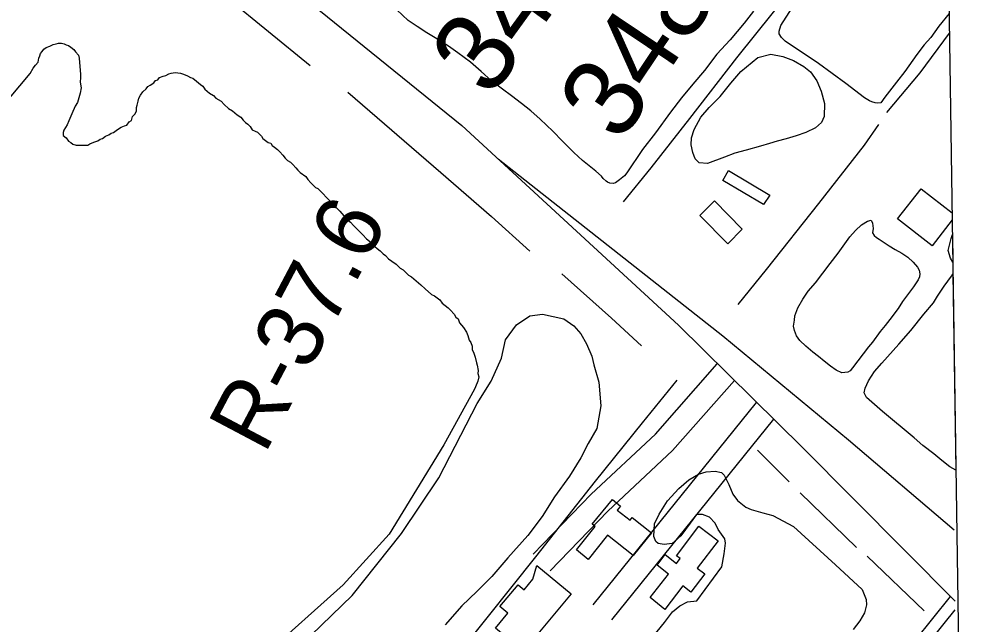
# Model space of a CAD drawing. Extents: x 3775218 to 3813389, y 343470 to 369318.
# Drawn here: x 3810057 to 3811247, y 351933 to 352694 of the extents above; entities that cross this region are included whole.
import ezdxf

# ---------------------------------------------------------------- set-up
doc = ezdxf.new("R2010")
doc.units = 0
for name, color, linetype in [('V-BLDG-OTLN', 7, 'Continuous'), ('V-GRID-FRAM', 7, 'Continuous'), ('V-RIVR-RANG-IDEN', 7, 'Continuous'), ('V-ROAD-CNTR', 7, 'Continuous'), ('V-SITE-VEGE', 7, 'Continuous'), ('V-SURV-IDEN', 7, 'Continuous'), ('V-TOPO-SHOR', 7, 'Continuous')]:
    doc.layers.add(name, color=color, linetype=linetype)

msp = doc.modelspace()

# ---------------------------------------------------------------- linework, layer by layer
at = {"layer": 'V-BLDG-OTLN'}
for p, q in [((3811163.1, 352442.5), (3811192.7, 352480.4)), ((3811192.7, 352480.4), (3811231.7, 352450)), ((3811231.7, 352450), (3811231.8, 352441.3)), ((3811206.5, 352408.7), (3811163.1, 352442.5)), ((3811231.8, 352441.3), (3811206.5, 352408.7))]:
    msp.add_line(p, q, dxfattribs=at)
for points in [[(3810994.2, 352460.4), (3810943, 352490.8), (3810950.4, 352503.2), (3811002.2, 352472.5)], [(3810949.6, 352411.1), (3810914.4, 352446.9), (3810932.7, 352465), (3810967.7, 352429.5)], [(3810830.2, 352019), (3810798, 352044.6), (3810773.8, 352014.2), (3810758.9, 352026.1), (3810782.4, 352055.7), (3810778.8, 352058.5), (3810804.2, 352089.5), (3810814.4, 352081.3), (3810810.4, 352076.3), (3810826.5, 352063.6), (3810829.1, 352066.9), (3810853.5, 352047.6)], [(3810870.1, 351951), (3810851.6, 351966.3), (3810874.8, 351995.6), (3810860.5, 352007.1), (3810870.8, 352020.2), (3810884.7, 352009.2), (3810889.4, 352015.2), (3810884.7, 352018.9), (3810913, 352056.1), (3810937.2, 352037.6), (3810911, 352003.3), (3810920.5, 351996), (3810903, 351973.1), (3810892.9, 351980.9)], [(3810752.4, 351970.7), (3810704.2, 351913.1), (3810694.4, 351921.3), (3810682.2, 351906.7), (3810656.9, 351927.8), (3810672.6, 351946.7), (3810662.6, 351955), (3810685.5, 351982.3), (3810693.2, 351975.9), (3810704.2, 351989.2), (3810709, 352006.7)]]:
    msp.add_lwpolyline(points, close=True, dxfattribs=at)
at = {"layer": 'V-GRID-FRAM'}
msp.add_lwpolyline([(3779203.7, 367073.2), (3811012.4, 367522), (3811276.9, 349341.6), (3779452.3, 348892.5), (3779203.7, 367073.2)], dxfattribs=at)
at = {"layer": 'V-ROAD-CNTR'}
for points in [[(3808873.9, 353964.1), (3810010.7, 353048.5), (3810614.6, 352560.1), (3810887.2, 352308.6), (3811043.3, 352154.9), (3811235.5, 351961.5)], [(3811234.2, 352050.9), (3811101.2, 352164.1), (3810943.3, 352295), (3810660.6, 352517.6)], [(3810704.3, 352020.6), (3810777.4, 352096.4), (3810858.4, 352171.9), (3810936.2, 352260.3)], [(3810725.9, 351999.7), (3810798.4, 352075), (3810879.9, 352151), (3810957.7, 352239.2)], [(3810780, 351957.2), (3810985.7, 352211.6)], [(3810803.3, 351938.3), (3811007.2, 352190.4)], [(3810896, 351552.5), (3811229.6, 351967.4)], [(3810907.7, 351543.1), (3811235.6, 351950.9)]]:
    msp.add_lwpolyline(points, dxfattribs=at)
at = {"layer": 'V-SITE-VEGE'}
for p, q in [((3810547.3, 352692.1), (3810533, 352705.6)), ((3810981.7, 352703.7), (3810970.1, 352688.5)), ((3811016.2, 352685.5), (3811030.3, 352707.9)), ((3811228, 352700.6), (3811215.1, 352684.7)), ((3810558.5, 352684.6), (3810547.3, 352692.1)), ((3810970.1, 352688.5), (3810952.3, 352667.7)), ((3811014.1, 352678.4), (3811016.2, 352685.5)), ((3810570.7, 352676.4), (3810558.5, 352684.6)), ((3810581.1, 352670.3), (3810570.7, 352676.4)), ((3811014.2, 352675.1), (3811014.1, 352678.4)), ((3811016.9, 352670.4), (3811014.2, 352675.1)), ((3811215.1, 352684.7), (3811205, 352670.8)), ((3810597.8, 352659.6), (3810581.1, 352670.3)), ((3810952.3, 352667.7), (3810935.7, 352649.8)), ((3811021.7, 352666.2), (3811016.9, 352670.4)), ((3811063.6, 352637.8), (3811021.7, 352666.2)), ((3811205, 352670.8), (3811196.6, 352661.3)), ((3810609.8, 352651.3), (3810597.8, 352659.6)), ((3810625.4, 352639.5), (3810609.8, 352651.3)), ((3810935.7, 352649.8), (3810920.1, 352629.3)), ((3811196.6, 352661.3), (3811187.4, 352649.4)), ((3810639.1, 352627.7), (3810625.4, 352639.5)), ((3811187.4, 352649.4), (3811172.1, 352627.7)), ((3810652.2, 352615.9), (3810639.1, 352627.7)), ((3810920.1, 352629.3), (3810905.6, 352612)), ((3811098, 352612.9), (3811063.6, 352637.8)), ((3811172.1, 352627.7), (3811161.9, 352614.4)), ((3810665.7, 352605.7), (3810652.2, 352615.9)), ((3811161.9, 352614.4), (3811147.2, 352595.7)), ((3810677.3, 352597.4), (3810665.7, 352605.7)), ((3810905.6, 352612), (3810891, 352594.8)), ((3811121.7, 352594.6), (3811098, 352612.9)), ((3810689.8, 352587.8), (3810677.3, 352597.4)), ((3810891, 352594.8), (3810877.4, 352576.7)), ((3811127.8, 352590.8), (3811121.7, 352594.6)), ((3811130.7, 352589.9), (3811127.8, 352590.8)), ((3811147.2, 352595.7), (3811142, 352588.4)), ((3810701.6, 352578.2), (3810689.8, 352587.8)), ((3811135, 352588.5), (3811130.7, 352589.9)), ((3811137.3, 352588.2), (3811135, 352588.5)), ((3811142, 352588.4), (3811137.3, 352588.2)), ((3810713.3, 352568), (3810701.6, 352578.2)), ((3810729.3, 352552.6), (3810713.3, 352568)), ((3810877.4, 352576.7), (3810858.3, 352550.6)), ((3810741.4, 352540.4), (3810729.3, 352552.6)), ((3810858.3, 352550.6), (3810842, 352529.6)), ((3810755.6, 352525.9), (3810741.4, 352540.4)), ((3810766.6, 352515.9), (3810755.6, 352525.9)), ((3810842, 352529.6), (3810822.3, 352500.2)), ((3810783.4, 352502.5), (3810766.6, 352515.9)), ((3810790.5, 352496.4), (3810783.4, 352502.5)), ((3810792.7, 352493.2), (3810790.5, 352496.4)), ((3810819.6, 352496.7), (3810813.2, 352491.7)), ((3810822.3, 352500.2), (3810819.6, 352496.7)), ((3810796.2, 352490), (3810792.7, 352493.2)), ((3810798.1, 352488.6), (3810796.2, 352490)), ((3810801, 352487.2), (3810798.1, 352488.6)), ((3810805.3, 352486.9), (3810801, 352487.2)), ((3810808.1, 352487.9), (3810805.3, 352486.9)), ((3810813.2, 352491.7), (3810808.1, 352487.9)), ((3811227, 352402.7), (3811230.7, 352417.9)), ((3811230.7, 352417.9), (3811232.1, 352422.7)), ((3811232.1, 352422.7), (3811232.6, 352388.1)), ((3811229.8, 352393.1), (3811227, 352402.7)), ((3811232.6, 352388.1), (3811229.8, 352393.1)), ((3811221.9, 352357.8), (3811231.1, 352370.6)), ((3811231.1, 352370.6), (3811232.8, 352373.2)), ((3811232.8, 352373.2), (3811236.4, 352126.3)), ((3811213.2, 352345.4), (3811221.9, 352357.8)), ((3811208.2, 352336.9), (3811213.2, 352345.4)), ((3811196.2, 352322.6), (3811208.2, 352336.9)), ((3811179.7, 352302.2), (3811196.2, 352322.6)), ((3811164.7, 352284.9), (3811179.7, 352302.2)), ((3811143.2, 352261), (3811164.7, 352284.9)), ((3811133.9, 352250.4), (3811143.2, 352261)), ((3811126.5, 352238.8), (3811133.9, 352250.4)), ((3811122.2, 352229.7), (3811126.5, 352238.8)), ((3811121.1, 352223.6), (3811122.2, 352229.7)), ((3811124.1, 352217.9), (3811121.1, 352223.6)), ((3811134, 352208.9), (3811124.1, 352217.9)), ((3811144, 352200.3), (3811134, 352208.9)), ((3811183.9, 352167.2), (3811144, 352200.3)), ((3811195.1, 352157.6), (3811183.9, 352167.2)), ((3811208.6, 352147), (3811195.1, 352157.6)), ((3811219, 352138.4), (3811208.6, 352147)), ((3811229, 352130.8), (3811219, 352138.4)), ((3811236.4, 352126.3), (3811229, 352130.8))]:
    msp.add_line(p, q, dxfattribs=at)
for points in [[(3810923.9, 352512.1), (3810913.3, 352512.9), (3810908.3, 352517.9), (3810905.5, 352525.8), (3810903.3, 352535.6), (3810903.9, 352544.6), (3810907.2, 352554.9), (3810915.5, 352570.4), (3810926.1, 352582.4), (3810939.7, 352596.2), (3810953.1, 352613.2), (3810965.9, 352628), (3810987.4, 352645.5), (3811003.5, 352649.5), (3811018.8, 352646.8), (3811032.2, 352641.5), (3811045, 352634.2), (3811053.5, 352627.4), (3811061.5, 352615.9), (3811066.9, 352602.9), (3811071.1, 352587.7), (3811070.8, 352571.3), (3811067.3, 352563.7), (3811059.8, 352556.8), (3811047.7, 352551.3), (3811035.3, 352547.1), (3811022.7, 352543.2), (3811011.7, 352540.1), (3811002, 352537.1), (3810990.6, 352534), (3810972.7, 352528.7), (3810958.2, 352525), (3810945.5, 352520)], [(3811106.5, 352255.3), (3811103.6, 352251.5), (3811100.6, 352249.8), (3811092.9, 352248.8), (3811085.8, 352252.3), (3811078.7, 352257.4), (3811070.9, 352263.4), (3811063.5, 352269.3), (3811056.6, 352274.7), (3811047.8, 352282.3), (3811040.3, 352289.4), (3811036, 352295.4), (3811033.4, 352302.3), (3811032.3, 352307.6), (3811033.2, 352315.2), (3811033.8, 352320.5), (3811037.5, 352330.5), (3811043.7, 352341.4), (3811050.8, 352351.4), (3811059.8, 352362.1), (3811078.3, 352386.5), (3811088.4, 352399.2), (3811103, 352419.7), (3811110, 352428), (3811117.7, 352435.2), (3811125.1, 352439.6), (3811129.9, 352440.9), (3811131.5, 352437.1), (3811132.4, 352430.2), (3811131.4, 352425), (3811133.8, 352421.4), (3811136.6, 352418.9), (3811139.9, 352416.9), (3811152.5, 352408.7), (3811160.1, 352404), (3811168.3, 352399.4), (3811176, 352394.2), (3811182.6, 352387.9), (3811188.1, 352381.9), (3811190.3, 352377.9), (3811191, 352373.4), (3811190.6, 352369.6), (3811188.9, 352365.8), (3811186.6, 352362), (3811183.1, 352357.1), (3811169.4, 352338.4), (3811163.7, 352329.9), (3811153.4, 352315.9), (3811147.3, 352308.5), (3811141.4, 352301), (3811131.7, 352287.4), (3811126.7, 352281.4)]]:
    msp.add_lwpolyline(points, close=True, dxfattribs=at)
for points in [[(3810476.5, 351968.7), (3810538.7, 352046.6), (3810585.8, 352117), (3810633.9, 352210.1), (3810651.8, 352238.2), (3810664.5, 352267.5), (3810669.6, 352290.5), (3810683.6, 352309.1), (3810700.2, 352320.4), (3810716.2, 352322.7), (3810743.2, 352316.9), (3810755.6, 352307.8), (3810764.5, 352297.8), (3810771.4, 352285.3), (3810778.2, 352269.8), (3810780.9, 352259.1), (3810787, 352237), (3810789.7, 352207.2), (3810784.6, 352178.7), (3810773.9, 352159.9), (3810764.3, 352141.8), (3810750, 352118.8), (3810731.3, 352092.9), (3810715.9, 352068.1), (3810697.7, 352044.4), (3810672.4, 352016.2), (3810652.4, 351992.8), (3810633.4, 351973.8), (3810614.6, 351955.8), (3810593.7, 351932)], [(3810851.2, 351912.3), (3810869.6, 351934.9), (3810880, 351948.4), (3810889, 351955.8), (3810898.7, 351961), (3810910.5, 351962), (3810942, 352004.7), (3810945, 352021), (3810946.4, 352034.5), (3810945.6, 352040), (3810937.3, 352051.8), (3810933.4, 352059.7), (3810926.3, 352067.4), (3810917.5, 352070.8), (3810910, 352070.8), (3810902.2, 352059.7), (3810890.2, 352043.7), (3810879.5, 352034.4), (3810869.5, 352032.8), (3810861.6, 352034), (3810858.9, 352036.7), (3810856.3, 352043.2), (3810857.1, 352058.9), (3810863.2, 352071.1), (3810873.7, 352087.7), (3810887.8, 352103.5), (3810900.2, 352114.4), (3810912.4, 352121.4), (3810922.4, 352124.5), (3810933.7, 352125.2), (3810941.4, 352123.4), (3810944.8, 352120), (3810950.9, 352108.3), (3810955.9, 352096.2), (3810961.6, 352088.1), (3810972, 352080), (3810979, 352077.1), (3810993.5, 352072.9), (3811006.1, 352069.6), (3811032.3, 352055.6), (3811084.9, 352007.5), (3811118.7, 351976.4), (3811123.8, 351963.6), (3811123.9, 351957), (3811121.5, 351947), (3811115.8, 351936.8), (3811107.2, 351925.9)], [(3810036, 351545.4), (3810109.4, 351638), (3810184.7, 351716.6), (3810272.8, 351796.9), (3810354.8, 351867.8), (3810425, 351919.1), (3810476.5, 351968.7)]]:
    msp.add_lwpolyline(points, dxfattribs=at)
at = {"layer": 'V-TOPO-SHOR'}
for p, q in [((3810292.4, 352743), (3810423.8, 352635.4)), ((3810987, 352151.5), (3811026.8, 352111.9)), ((3811040.7, 352098.1), (3811111.4, 352029.2)), ((3811125, 352018.2), (3811196.5, 351949.7))]:
    msp.add_line(p, q, dxfattribs=at)
for points in [[(3810818.2, 352464), (3810852.9, 352506.5), (3810901.8, 352568.6), (3810961, 352644.9), (3811029.3, 352730.7), (3811108.4, 352829.7), (3811160.3, 352895), (3811217.9, 352969.1), (3811224, 352976.9)], [(3811149.8, 352576.3), (3811191.7, 352626.3), (3811228.4, 352676)], [(3810086.5, 352653.2), (3810088.5, 352656.1), (3810091.4, 352658), (3810096.3, 352659.9), (3810100.3, 352661.7), (3810104.2, 352662.6), (3810107.1, 352663.6), (3810111, 352663.5), (3810114, 352662.5), (3810116.9, 352661.4), (3810119.8, 352660.4), (3810122.7, 352658.4), (3810126.5, 352655.4), (3810128.4, 352652.4), (3810132.2, 352648.5), (3810133.1, 352644.5), (3810134.7, 352624), (3810134.6, 352620.1), (3810134.5, 352614.3), (3810135.4, 352607.4), (3810134.3, 352600.6), (3810131.1, 352589), (3810128.1, 352584.2), (3810124, 352574.5), (3810120, 352565.8), (3810117.9, 352560.9), (3810113.9, 352554.2), (3810112.9, 352551.3), (3810112.8, 352547.4), (3810116.6, 352544.4), (3810119.5, 352540.4), (3810122.4, 352538.4), (3810125.3, 352536.4), (3810129.1, 352535.4), (3810134, 352535.3), (3810137.9, 352535.2), (3810143.8, 352535.1), (3810146.7, 352537), (3810151.7, 352538.8), (3810156.6, 352540.7), (3810159.5, 352542.6), (3810162.5, 352543.5), (3810166.4, 352546.4), (3810170.4, 352548.2), (3810173.3, 352550.1), (3810176.3, 352551.1), (3810181.2, 352554.9), (3810186.1, 352557.7), (3810190.1, 352559.6), (3810193, 352560.5), (3810196, 352564.4), (3810199, 352566.2), (3810200.1, 352571.1), (3810203, 352574), (3810205.1, 352577.8), (3810205.1, 352582.7), (3810206.2, 352585.6), (3810207.2, 352590.5), (3810208.3, 352594.4), (3810210.3, 352598.2), (3810213.3, 352602.1), (3810217.3, 352605.9), (3810219.3, 352608.8), (3810222.3, 352610.7), (3810227.2, 352613.5), (3810229.2, 352616.4), (3810232.1, 352617.3), (3810234.1, 352620.2), (3810239, 352622.1), (3810242, 352623), (3810245.9, 352624.9), (3810248.9, 352625.8), (3810253.8, 352626.7), (3810260.6, 352625.6), (3810264.5, 352624.5), (3810269.3, 352622.5), (3810273.2, 352620.5), (3810276.1, 352619.4), (3810280.9, 352615.5), (3810285.7, 352611.5), (3810288.6, 352609.5), (3810291.4, 352605.5), (3810297.2, 352600.5), (3810302, 352597.5), (3810304.9, 352594.5), (3810311.6, 352590.5), (3810315.5, 352586.5), (3810321.2, 352581.5), (3810326, 352578.5), (3810331.8, 352573.5), (3810336.6, 352570.5), (3810339.5, 352566.6), (3810342.3, 352563.6), (3810345.2, 352561.6), (3810348.1, 352558.6), (3810351, 352554.6), (3810354.8, 352552.6), (3810357.7, 352551.6)], [(3810045.4, 352594.5), (3810071.3, 352625.2), (3810075.3, 352632), (3810078.3, 352635.8), (3810081.3, 352639.7), (3810082.4, 352644.5), (3810083.4, 352647.4), (3810084.5, 352650.3), (3810086.5, 352653.2)], [(3810471.3, 352601.7), (3810588.4, 352500.8), (3810651.9, 352445.4), (3810700.4, 352402)], [(3810962.6, 352334.8), (3810998.2, 352378.9), (3811063.9, 352461.9), (3811121.6, 352535.3), (3811139.5, 352561.2)], [(3810357.7, 352551.6), (3810362.5, 352546.6), (3810364.4, 352543.7), (3810371.1, 352538.7), (3810374.1, 352537.6), (3810376, 352534.7), (3810378.8, 352532.7), (3810382.7, 352529.7), (3810385.6, 352526.7), (3810389.4, 352522.7), (3810392.2, 352518.8), (3810395.1, 352515.8), (3810399, 352513.8), (3810401.8, 352510.8), (3810405.7, 352506.8), (3810408.5, 352503.8), (3810411.4, 352500.8), (3810418.2, 352495.8), (3810421, 352491.9), (3810424.8, 352487.9), (3810430.6, 352481.9), (3810433.5, 352480.9), (3810437.3, 352476.9), (3810440.2, 352474), (3810444, 352470), (3810446.9, 352467), (3810451.7, 352462), (3810457.4, 352456.1), (3810461.2, 352452.1), (3810466, 352446.2), (3810470.8, 352441.2), (3810474.6, 352438.2), (3810478.5, 352434.2), (3810481.3, 352431.2), (3810485.2, 352427.3), (3810490, 352422.3), (3810494.7, 352417.3), (3810498.6, 352414.3), (3810502.4, 352410.4), (3810508.2, 352405.4), (3810512, 352402.4), (3810515.9, 352398.4), (3810518.7, 352396.4), (3810522.6, 352392.4), (3810526.4, 352389.4), (3810532.2, 352385.4), (3810537, 352380.5), (3810540.8, 352378.4), (3810544.7, 352374.5), (3810547.5, 352371.5), (3810551.4, 352369.5), (3810557.2, 352364.5), (3810562.9, 352359.5), (3810568.7, 352354.5), (3810576.4, 352347.5), (3810580.2, 352345.5), (3810587, 352340.5), (3810589.8, 352336.6), (3810593.7, 352333.6), (3810597.5, 352330.6), (3810600.4, 352327.6), (3810605.2, 352322.6), (3810607, 352318.7), (3810609.9, 352316.7), (3810611.8, 352311.8), (3810616.6, 352305.8), (3810620.4, 352299.9), (3810622.2, 352295.9), (3810624.1, 352290.1), (3810626, 352287.1), (3810627.8, 352282.2), (3810627.8, 352278.3), (3810629.6, 352273.4), (3810631.5, 352268.5), (3810633.3, 352261.6), (3810634.2, 352258.7), (3810635.1, 352251.8), (3810635, 352247.9), (3810635.9, 352244), (3810634.8, 352238.2), (3810631.8, 352231.4), (3810630.7, 352228.5), (3810592, 352158.5), (3810523.1, 352046), (3810465.5, 351982.3)], [(3810740.6, 352373.2), (3810803.1, 352317.6), (3810840.8, 352282.9)], [(3809932.2, 351139.9), (3809957.2, 351149.5), (3810017.4, 351172.9), (3810062, 351193.1), (3810076.8, 351203.6), (3810088, 351215.9), (3810098.3, 351227.4), (3810109.9, 351240.8), (3810128.3, 351275.2), (3810163.5, 351338.7), (3810207, 351392.5), (3810292.5, 351501), (3810374.5, 351602.2), (3810447.4, 351692.5), (3810517.6, 351780.7), (3810616.6, 351903.2), (3810707.8, 352017.5), (3810783, 352112.6), (3810842, 352185.9), (3810885.9, 352239.5)], [(3810465.5, 351982.3), (3810365, 351892.7)]]:
    msp.add_lwpolyline(points, dxfattribs=at)

# ---------------------------------------------------------------- texts
at = {"layer": 'V-RIVR-RANG-IDEN'}
msp.add_text('R-37.6', height=83, rotation=62.1413, dxfattribs=at).set_placement((3810366.5, 352145.1))
at = {"layer": 'V-SURV-IDEN'}
for s, rotation, p in [('346+70.9', 54.0525, (3810650.3, 352592.6)), ('348+10.0', 56.122, (3810813.9, 352536.1))]:
    msp.add_text(s, height=100, rotation=rotation, dxfattribs=at).set_placement(p)

doc.saveas('drawing.dxf')
